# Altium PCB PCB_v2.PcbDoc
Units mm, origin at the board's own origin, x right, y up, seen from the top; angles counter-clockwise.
Board outline 61.5 x 35 mm, 2 copper layers (Top Layer, Bottom Layer); 42 components, 41 nets, 172 pads, 28 vias.
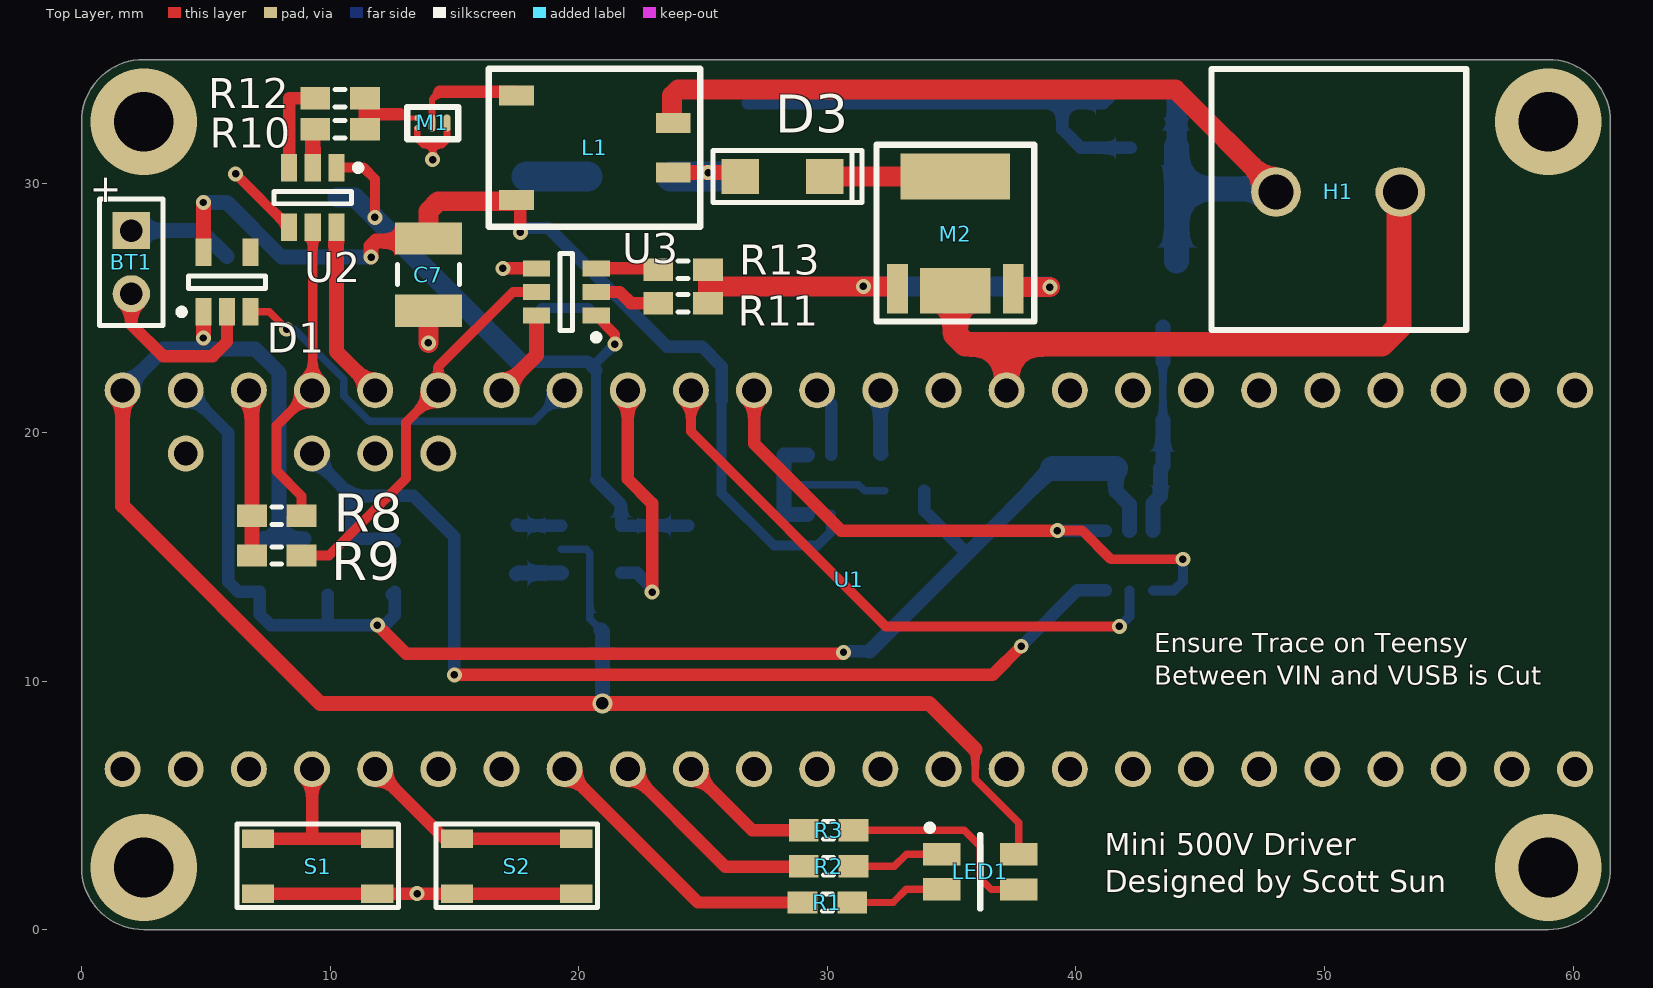
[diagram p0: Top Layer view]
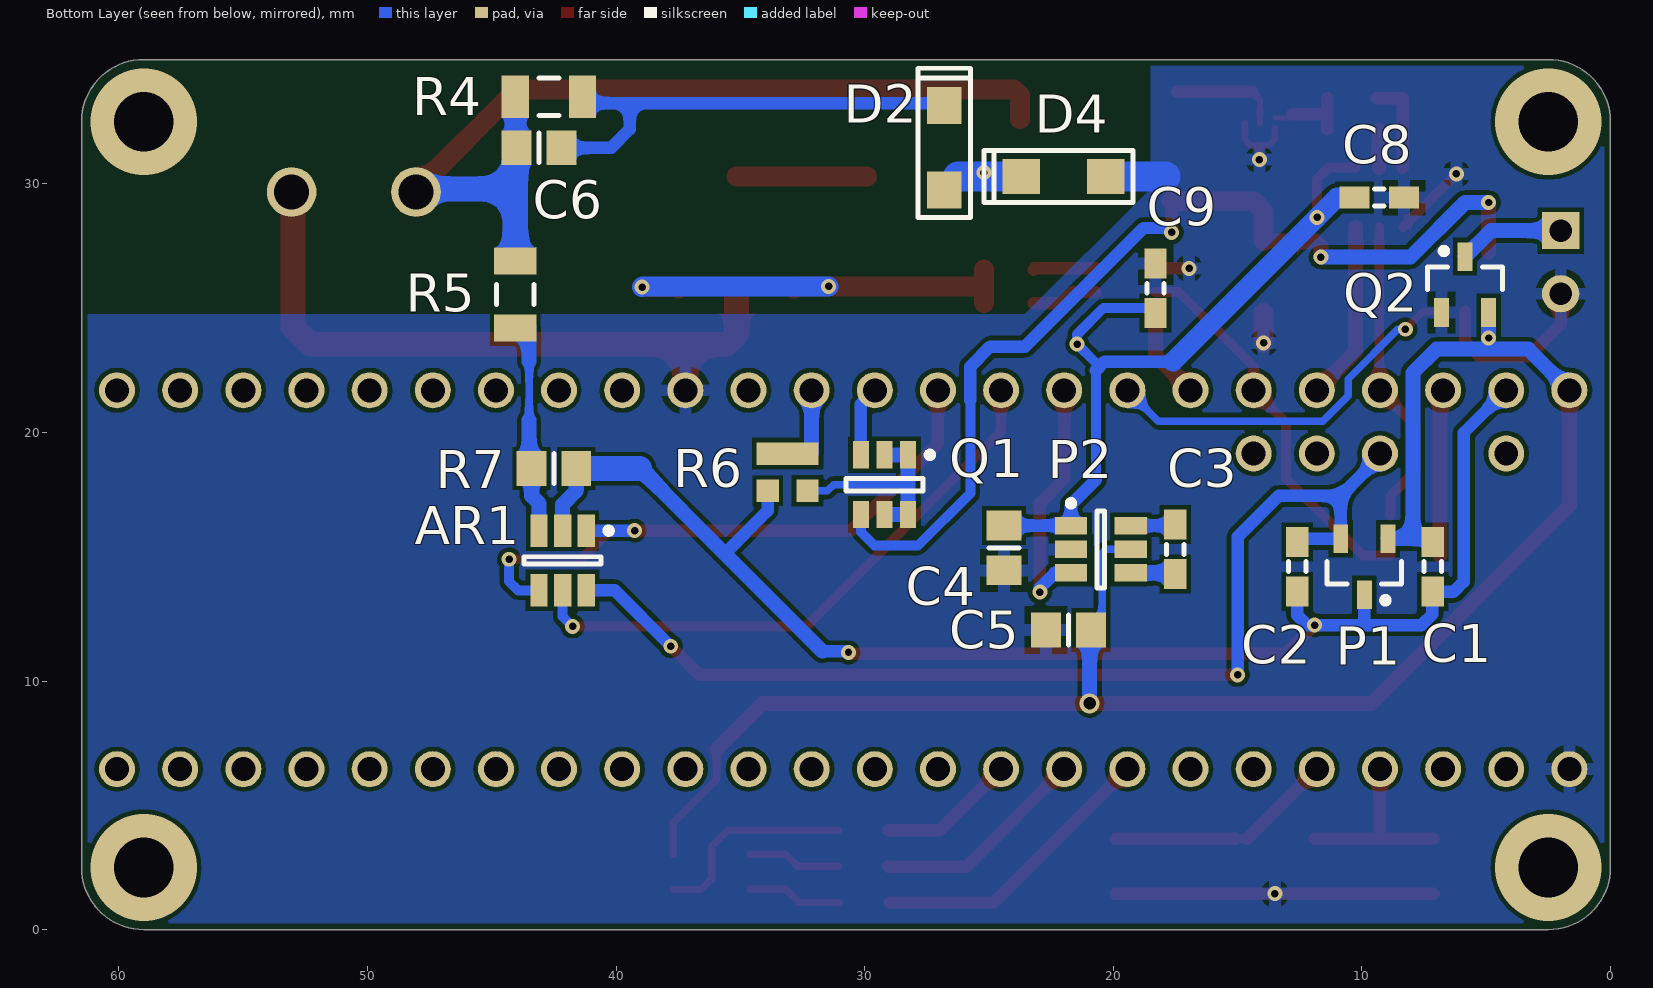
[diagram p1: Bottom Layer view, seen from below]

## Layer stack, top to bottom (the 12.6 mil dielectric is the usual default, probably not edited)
Top Solder: solder mask 0.0102, Solder Resist, Dk 3.5
Top Layer: signal copper 0.0356
Dielectric 1: dielectric 0.32, FR-4, Dk 4.8
Bottom Layer: signal copper 0.0356
Bottom Solder: solder mask 0.0102, Solder Resist, Dk 3.5

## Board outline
59,35 cw(c59,32.5) 61.5,32.5 61.5,2.5 cw(c59,2.5) 59,0 2.5,0 cw(c2.5,2.5) 0,2.5 0,32.5 cw(c2.5,32.5) 2.5,35

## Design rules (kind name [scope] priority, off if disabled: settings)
BoardOutlineClearance [All] p1: gap=0.2 ignorepadtopadclearanceinfootprint=FALSE
Clearance [All] p1: gap=0.178 ignorepadtopadclearanceinfootprint=FALSE
ComponentClearance ComponentClearance_1 [InComponent('U1')] p1: gap=0 collisioncheckmode=3 verticalgap=0 showdistances=FALSE
ComponentClearance [All] p2: gap=0.254 collisioncheckmode=3 verticalgap=0.254 showdistances=FALSE
HoleSize [All] p1: absolutevalues=TRUE maxlimit=2.54 minlimit=0.2 maxpercent=80.000 minpercent=20.000
MinimumAnnularRing [All] p1: minimumring=0.076
MinimumSolderMaskSliver [All] p1: minsoldermaskwidth=0.1
PolygonConnect [All] p1: connectstyle=Relief reliefconductorwidth=0.5 reliefentries=4 polygonreliefangle="90 Angle" airgapwidth=0.254
RoutingVias [All] p1: holewidth=1.5 width=1.27 viastyle="Through Hole" minholewidth=0.127 minwidth=0.3 maxholewidth=2.54 maxwidth=5
SolderMaskExpansion [All] p1: expansion=0.102
Width [All] p1: maxlimit=2 minlimit=0.1 preferedwidth=0.2
27 further rules are at their usual default settings.

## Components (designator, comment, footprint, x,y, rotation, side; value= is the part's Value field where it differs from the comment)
AR1 "OPA320" SOT23-6_M 42.15,14.85 r270 bottom
BT1 "Battery" BAT-2 2,26.85 r270 top
C1 "Cap Semi" 0603 7.15,14.6 r90 bottom value=100nF
C2 "Cap Semi" 0603 12.6,14.6 r90 bottom value=100nF
C3 "Cap Semi" 0603 17.5,15.3 r90 bottom value=1uF
C4 "Cap Semi" 6-0805_N 24.396,15.354 r90 bottom value=22uF
C5 "Cap Semi" 6-0805_N 21.8,12.05 r180 bottom value=10uF
C6 "Cap Semi" 6-0805_N 43.1,31.45 r0 bottom value=1nF
C7 "Cap Semi" C1210_N 13.95,26.35 r90 top value=100uF
C8 "Cap Semi" 0603 9.3,29.45 r0 bottom value=100nF
C9 "Cap Semi" 0603 18.3,25.8 r270 bottom value=100nF
D1 "LTC4411" SOT23-5 5.85,26.05 r90 top
D2 "HS1MLWRVG" sub-SMA 26.8,31.45 r90 bottom
D3 "HS1MLWRVG" sub-SMA 28.2,30.3 r0 top
D4 "HS1MLWRVG" sub-SMA 22,30.3 r0 bottom
H1 "1792863 Block" PHX_BLOCK_SMALLER 48.05,29.673 r0 top
L1 "Coupled Inductor" "CJ5143 Inductor" 17.9,31.45 r0 top
LED1 "150141M173100" 3528_A 36.15,2.325 r0 top
M1 "EPC2012C" EPC2012C 13.5,32.246 r0 top
M2 "GS66506" GS66506T 35.15,29.8 r0 top
P1 "REF3033" SOT23_N 9.9,14.6 r270 bottom
P2 "LTC1754-5" SOT23-6_M 20.5,15.3 r180 bottom
Q1 "IRFTS9342TRPBF" SOT23-6_N 29.2,17.9 r270 bottom
Q2 "DMP1045U" SOT23_N 5.85,25.95 r90 bottom
R1 "Res1" 0603 30,1.091 r0 top value=400
R2 "Res1" 0603 30.05,2.546 r0 top value=400
R3 "Res1" 0603 30.05,4 r0 top value=400
R4 "Res1" C1206 42.7,33.5 r0 bottom value=20K
R5 "Res1" C1206 44.05,25.55 r90 bottom value=120M
R6 "R2012A" R2012A 31.8,19.6 r0 bottom
R7 "Res1" 6-0805_N 42.5,18.55 r0 bottom value=634K
R8 "Res1" 0603 7.85,16.65 r180 top value=100K
R9 "Res1" 0603 7.85,15.05 r180 top value=100K
R10 "Res1" 0603 10.4,32.2 r180 top value=5
R11 "Res1" 0603 24.2,25.2 r0 top value=10
R12 "Res1" 0603 10.4,33.45 r180 top value=1
R13 "Res1" 0603 24.2,26.55 r0 top value=4
S1 "TL3365" TL3365 9.45,2.45 r0 top
S2 "TL3365" TL3365 17.45,2.45 r0 top
U1 "Teensy 3.5" "Teensy 3.6" 31.75,13.95 r0 top
U2 "LM5114" SOT23-6_N 9.3,29.45 r270 top
U3 "LM5114" SOT23-6_N 19.5,25.65 r180 top

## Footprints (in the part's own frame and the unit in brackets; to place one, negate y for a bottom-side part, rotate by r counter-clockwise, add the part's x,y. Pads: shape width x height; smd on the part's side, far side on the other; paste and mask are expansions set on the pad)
6-0805_N [mm] "Chip Resistor, Body 2.0x1.2mm, IPC Medium Density"
  rect 1.2x1.4 smd: 1(-0.9,0) 2(0.9,0)
  silkscreen extent 0,-0.6 0,0.6, body extent -1.07,-0.7 1.07,0.7, height 0.7
0603 [mm]
  rect 1.2x0.9 smd: 1(-1,0) 2(1,0)
  silkscreen extent -0.2,-0.35 0.2,0.35, body extent -0.85,-0.47 0.85,0.48, height 0.9
3528_A [mm] "Chip LED, 4-Leads, Body 2.8x3.5mm (max), Pitch 1.42mm, IPC Medium Density"
  rect 1.5x0.9 smd: 1(1.55,0.707) 2(1.55,-0.71) 3(-1.55,0.707) 4(-1.55,-0.707)
  silkscreen extent -2.15,-1.5 0.03,1.9, body extent -1.75,-1.4 1.75,1.4, height 1.87
BAT-2 [mm] "Battery; 2 Leads"
  rect 1.5x1.5 hole 0.9: 1(-1.27,0)
  round 1.5 hole 0.9: 2(1.27,0)
  silkscreen extent -2.54,-1.27 2.54,1.27
C1206 [mm] "Chip Capacitor, Body 3.2x1.6mm, IPC High Density"
  rect 1.1x1.7 smd: 1(-1.35,0) 2(1.35,0)
  silkscreen extent -0.4,-0.75 0.4,0.75, body extent -1.7,-0.9 1.7,0.9, height 1.3
C1210_N [mm] "Chip Capacitor, Body 3.2x2.5mm, IPC Medium Density"
  rect 1.3x2.7 smd: 1(-1.45,0) 2(1.45,0)
  silkscreen extent -0.4,-1.25 0.4,1.25, body extent -1.7,-1.35 1.7,1.35, height 1.5
"CJ5143 Inductor" [mm]
  rect 1.4x0.8 smd: 1(-0.4,-2.1) 4(-0.4,2.1) 5(5.9,1) 6(5.9,-1)
  silkscreen extent -1.52,-3.17 6.98,3.17
EPC2012C [mm]
  round 0.234 smd mask+0.01: 1(0,0.409) 2(0,0)
  oval 0.284x0.693 smd mask-0.025: 3(0.6,0.205) 4(1.2,0.205)
  silkscreen extent -0.4,-0.45 1.65,0.85
GS66506T [mm]
  rect 4.4x1.84 smd: 1(0,0.5)
  rect 0.84x1.99 smd: 2(-2.33,-4.02) 4(2.33,-4.02)
  rect 2.83x1.84 smd: 3(0,-4.1)
  silkscreen extent -3.17,-5.33 3.17,1.78
PHX_BLOCK_SMALLER [mm]
  round 2 hole 1.4: 1(0,0) 2(5,0)
  silkscreen extent -2.6,-5.55 7.65,4.95
R2012A [mm] "Voltage Divider 0805 Footprint"
  rect 0.9x0.9 smd: 1(0.5,1.95) 3(2.1,1.95)
  rect 2.5x0.9 smd: 2(1.3,0.45)
  body extent 0.23,0.5 2.37,1.9, height 0.7
SOT23-5 [mm]
  rect 1.1x0.65 smd: 1(-1.2,0.95) 2(-1.2,0) 3(-1.2,-0.95) 4(1.2,-0.95) 5(1.2,0.95)
  silkscreen extent -1.32,-1.55 0.25,1.95, body extent -0.9,-1.55 0.9,1.55, height 1.45
SOT23-6_M [mm] "SOT23, 6-Leads, Body 2.9x1.6mm, Pitch 0.95mm, Lead Span 2.7mm, IPC Low Density"
  rect 1.3x0.7 smd: 1(-1.2,0.95) 2(-1.2,0) 3(-1.2,-0.95) 4(1.2,-0.95) 5(1.2,0) 6(1.2,0.95)
  silkscreen extent -1.32,-1.55 0.15,1.97, body extent -0.9,-1.55 0.9,1.55, height 1.45
SOT23-6_N [mm] "SOT23, 6-Leads, Body 2.9x1.6mm, Pitch 0.95mm, Lead Span 2.7mm, IPC Medium Density"
  rect 1.1x0.65 smd: 1(-1.2,0.95) 2(-1.2,0) 3(-1.2,-0.95) 4(1.2,-0.95) 5(1.2,0) 6(1.2,0.95)
  silkscreen extent -1.32,-1.55 0.25,1.95, body extent -0.9,-1.55 0.9,1.55, height 1.45
SOT23_N [mm] "SOT23, 3-Leads, Body 2.9x1.3mm, Pitch 0.95mm, Lead Span 2.3mm - Reverse Pinning, IPC Medium Density"
  rect 1.15x0.6 smd: 1(1.125,0) 2(-1.125,-0.95) 3(-1.125,0.95)
  silkscreen extent -0.2,-1.5 1.47,1.5, body extent -0.7,-1.5 0.7,1.5, height 1.1
sub-SMA [mm]
  rect 1.5x1.4 smd: A(-1.7,0) K(1.7,0)
  silkscreen extent -2.8,-1.05 3.2,1.05
"Teensy 3.6" [mil]
  round 57 hole 38: 0/RX(-1085,-295) 1/TX(-985,-295) 2(-885,-295) 3/CANTX(-785,-295) 3V3(215,-295) 3V3_LO(-985,305) 4/CANRX(-685,-295) 5(-585,-295) 6(-485,-295) 7(-385,-295) 8(-285,-295) 9/CS(-185,-295) 10/CS(-85,-295) 11/MOSI(15,-295) 12/MISO(115,-295) 13/SCK(115,305) 14/A0(15,305) 15/A1(-85,305) 16/A2(-185,305) 17/A3(-285,305) 18/A4/SDA(-385,305) 19/A5/SCL(-485,305) 20/A6(-585,305) 21/A7(-685,305) 21/DAC0(415,305) 22/A8(-785,305) 23/A9(-885,305) 24(315,-295) 25(415,-295) 26(515,-295) 27(615,-295) 28(715,-295) 29(815,-295) 30(915,-295) 31/A12(1015,-295) 32/A13(1115,-295) 33/A14(1115,305) 34/A15(1015,305) 35/A16(915,305) 36/A17(815,305) 37/A18(715,305) 38/A19(615,305) 39/A20(515,305) A10(-785,205) A11(-685,205) A22/DAC1(315,305) AGND(-1085,305) AREF(-885,205) GND(-1185,-295) GND2(215,305) VIN(-1185,305) VUSB(-1085,205)
TL3365 [mm] "Pushbutton"
  rect 1.3x0.75 smd: 1(-2.35,-1) 2(2.45,-1) 3(-2.35,1.2) 4(2.45,1.2)
  silkscreen extent -3.2,-1.55 3.3,1.8

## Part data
AR1: library part "OPA320 Op Amp", "FET Operational Amplifier"
BT1: "Multicell Battery"
C1 C2 C3 C4 C5 C6 C7 C8 C9: "Capacitor (Semiconductor SIM Model)"
D1: library part "LTC4411 Ideal Diode", "LTC4411 Ideal Diode"
D2 D3 D4: library part "HS1MLWRVG Diode", "1kV fast diode"
H1: library part "1792863 1X2 Block", "Terminal Block, 2-Pin, 1792863"
L1: library part "CJ5143 Coupled Inductor", "1:15 Coupled Inductor"
LED1: library part CMP-1431-00001-1, "SMD Full-Color Top LED, WL-SFTW, Red & Green & Blue", Color="Red & Green & Blue", Manufacturer="Wuerth Elektronik"
M1: library part "EPC2012C GaNFET", "200V GaNFET Die"
M2: library part "GS66506 GaNFET", "650V GaNFET"
P1: library part "REF3030 3V Reference", "3.3V Reference"
P2: library part "LTC1754-5 Charge Pump", "5V Charge Pump"
Q1: library part "IRFTS9342TRPBF MOSFET", "30V, 5.8A, P-Channel MOSFET"
Q2: library part "DMP1045U PMOS", "P-Channel MOSFET"
R1 R2 R3 R4 R5 R7 R8 R9 R10 R11 R12 R13: "Resistor"
R6: library part "R2012A Voltage Divider", "Voltage Divider"
S1 S2: library part "TL3365 Pushbutton", "Pushbutton"
U1: library part TEENSY_3.6, "Teensy 3.6 Microcontroller"
U2 U3: library part "LM5114 Gate Driver", "Gate Driver"

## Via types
v1: diameter 0.6, hole 0.3, Top Layer to Bottom Layer, 23 vias
v2: diameter 4.3, hole 2.4, Top Layer to Bottom Layer, 4 vias
v3: diameter 0.8, hole 0.5, Top Layer to Bottom Layer, 1 vias

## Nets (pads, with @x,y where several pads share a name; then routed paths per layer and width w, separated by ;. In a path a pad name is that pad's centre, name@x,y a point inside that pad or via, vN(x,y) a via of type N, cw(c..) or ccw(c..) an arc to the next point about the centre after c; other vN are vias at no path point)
3.3V: R8.2 R9.2 U1.3V3_LO | length 6.7
  Top Layer w0.6: U1.3V3_LO 6.85,21.578 R8.2 R9.2
5V: C4.2 C8.2 C9.2 P2.1 U2.1 U3.1 | length 32.4
  Top Layer w0.4: U2.1 11.35,30.65 11.8,30.2 v1(11.8,28.65) ; U3.1 21.45,23.95 v1(21.45,23.55)
  Bottom Layer w0.4: C9.2 18.5,25 20.4,25 21.45,23.95 v1(21.45,23.55) 20.75,22.85 ; 20.7,18.1 20.7,22.5
  Bottom Layer w0.5: 17.6,22.85 20.35,22.85 20.7,22.5 ; 20.7,18.1 21.7,17.1 P2.1 21.704,16.254 C4.2
  Bottom Layer w0.8: C8.2 11,29.45 v1(11.8,28.65) 17.6,22.85
5V_S\H\D\N\: P2.3 U1.18/A4/SDA | length 10.2
  Top Layer w0.5: U1.18/A4/SDA 21.971,18.129 22.95,17.15 v1(22.95,13.575)
  Bottom Layer w0.5: P2.3 22.35,14.35 22.95,13.75 v1(22.95,13.575)
A0: R6.2 U1.14/A0 | length 2.6
  Bottom Layer w0.6: U1.14/A0 32.131,19.169 R6.2@32.15,19.15
A2: AR1.1 AR1.4 U1.16/A2 | length 25.5
  Top Layer w0.4: v1(39.25,16.05) 40.25,16.05 41.4,14.9 v1(44.3,14.9)
  Top Layer w0.5: U1.16/A2 27.051,19.549 30.55,16.05 v1(39.25,16.05)
  Bottom Layer w0.4: AR1.4 43.95,13.65 44.3,14 v1(44.3,14.9)
  Bottom Layer w0.5: v1(39.25,16.05) AR1.1
A3.3V: AR1.6 C2.2 P1.2 U1.AREF | length 43.9
  Top Layer w0.5: v1(15,10.25) 36.65,10.25 v1(37.8,11.4)
  Bottom Layer w0.5: U1.AREF 9.271,19.029 10.85,17.45 ; C2.2 12.475,15.725 P1.2 10.85,17.45 ; v1(15,10.25) 15,15.8 13.35,17.45 10.85,17.45 ; v1(37.8,11.4) 40.05,13.65 AR1.6
AGND: AR1.2 C1.1 C2.1 P1.1 R6.3 R7.1 U1.AGND | length 58.1
  Top Layer w0.5: v1(11.9,12.25) 13.05,11.1 30.6,11.1 v1(30.65,11.15)
  Bottom Layer w0.5: U1.AGND 5.9,19.988 5.9,14 6.312,13.588 7.162,13.588 7.162,12.688 7.6,12.25 9.9,12.25 ; P1.1 9.9,12.25 ; C2.1@12.475,13.475 C2.1 12.6,12.65 12.2,12.25 v1(11.9,12.25) 9.9,12.25 ; v1(30.65,11.15) 30.7,11.2 31.7,11.2 ; R6.3 33.9,16.85 35.625,15.125
  Bottom Layer w0.6: 31.7,11.2 35.625,15.125 39.05,18.55 ; R7.1 41.6,17.65 42.15,17.1 AR1.2
  Bottom Layer w1: 39.05,18.55 R7.1
B\A\T\T\_\S\E\N\S\E\: Q1.3 U1.15/A1 | length 2.8
  Bottom Layer w0.5: U1.15/A1 30.15,21.138 Q1.3
D_SHDN: D1.3 U1.19/A5/SCL | length 15.4
  Top Layer w0.3: D1.3 7.55,24.85 v1(8.25,24.15)
  Bottom Layer w0.3: v1(8.25,24.15) 8.55,24.15 10.55,22.15 10.55,21.471 11.571,20.45 18.184,20.45 U1.19/A5/SCL
GND: BT1.2 C4.1 C5.1 C7.1 C8.1 C9.1 D1.2 D4.A H1.2 M1.2 M1.4 M2.3 P2.2 Q2.3 S1.1 S1.2 S2.1 S2.2 U1.GND U1.GND2 U2.4 U3.4 | length 58.4
  Top Layer w0.25: M1.2@13.5,32.235 13.5,31.8 13.75,31.55 14.125,31.55 ; v1(14.125,30.975) 14.125,31.55 ; M1.4 14.7,31.75 14.5,31.55 14.125,31.55
  Top Layer w0.4: v1(6.2,30.4) U2.4
  Top Layer w0.5: BT1.2 2,24.35 3.278,23.072 5.272,23.072 5.85,23.65 D1.2 ; S1.1 S1.2 v1(13.5,1.45) S2.1 S2.2 ; v1(16.95,26.6) U3.4
  Top Layer w0.8: v1(13.95,23.6) C7.1@13.95,24.8
  Top Layer w1: M2.3 35.15,23.95 35.55,23.55 37.211,23.55 ; U1.GND2 37.211,23.55 ; H1.2@53,29.8 53,24.25 52.3,23.55 37.211,23.55
  Bottom Layer w1.2: 17.9,30.3 D4.A D4.A@20.35,30.3
L\O\A\D\_\S\H\D\N\: AR1.5 U1.17/A3 | length 23.8
  Top Layer w0.4: U1.17/A3 24.511,20.039 32.35,12.2 v1(41.75,12.2)
  Bottom Layer w0.4: v1(41.75,12.2) 42.15,12.6 AR1.5
NetAR1_3: AR1.3 R5.1 R7.2 | length 8.4
  Bottom Layer w0.3: 43.5,20.5 43.5,22.85
  Bottom Layer w0.6: AR1.3 43.1,17.15 43.4,17.45 R7.2 43.5,18.65 43.5,20.5 ; 43.5,22.85 R5.1@43.5,24.25
NetBT1_1: BT1.1 Q2.1 | length 4.3
  Bottom Layer w0.6: BT1.1 4.805,28.12 Q2.1
NetC3_1: C3.1 P2.4 | length 1.8
  Bottom Layer w0.6: C3.1 17.55,14.35 P2.4
NetC3_2: C3.2 P2.6 | length 1.8
  Bottom Layer w0.5: C3.2 17.55,16.25 P2.6
NetC6_1: C6.1 D2.K R4.1 | length 18.8
  Bottom Layer w0.5: D2.K@26.8,33.25 39.45,33.25 ; R4.1 41.1,33.25 39.45,33.25 ; C6.1 40.2,31.45 39.45,32.2 39.45,33.25
NetC6_2: C6.2 H1.1 L1.5 R4.2 R5.2 | length 37.5
  Top Layer w0.8: L1.5@23.75,32.6 23.75,33.55 24,33.8 44,33.8 H1.1@48,29.8
  Bottom Layer w0.8: C6.2@44.05,31.5 R4.2
  Bottom Layer w1: R5.2 44.05,29.8 ; C6.2@44.05,31.5 44.05,29.8 ; H1.1@48,29.8 44.05,29.8
NetC7_2: C7.2 D1.5 L1.1 Q1.4 | length 40.6
  Top Layer w0.5: v1(17.65,28.05) L1.1@17.65,29.3
  Top Layer w0.6: D1.5 v1(4.9,29.25) ; v1(11.65,27.05) 11.65,27.5 11.85,27.7 C7.2@13.95,27.7
  Top Layer w0.8: C7.2@13.95,27.7 C7.2 13.95,28.9 14.35,29.3 L1.1@17.65,29.3
  Bottom Layer w0.4: 25.75,21.3 25.75,17.55 27.85,15.45 29.6,15.45 30.15,16 Q1.4
  Bottom Layer w0.5: v1(17.65,28.05) 17.825,28.225 18.775,28.225 23.55,23.45 24.95,23.45 25.75,22.65 25.75,21.3
  Bottom Layer w0.6: v1(4.9,29.25) 5.85,29.25 8.05,27.05 v1(11.65,27.05)
NetD2_A: D2.A D3.A D4.K L1.6 | length 6
  Top Layer w0.6: L1.6 v1(25.2,30.45) 25.9,30.45 26.05,30.3 D3.A
  Bottom Layer w0.6: D4.K@23.6,30.3 D4.K ; D2.A@26.25,30.3 D2.A@26.65,29.9
  Bottom Layer w1.2: D4.K D2.A@26.25,30.3
NetD3_K: D3.K M2.1 | length 5.3
  Top Layer w0.8: D3.K M2.1
NetL1_4: L1.4 M1.3 | length 4.4
  Top Layer w0.25: M1.3 14.1,33.4 14.4,33.7
  Top Layer w0.5: 14.4,33.7 L1.4@17.45,33.7
NetLED1_2: LED1.2 R3.2 | length 8.4
  Top Layer w0.3: R3.2 35.5,4 36.15,3.35 36.15,2.05 36.585,1.615 LED1.2
NetLED1_3: LED1.3 R2.2 | length 3.8
  Top Layer w0.3: R2.2 32.696,2.546 33.183,3.033 LED1.3
NetLED1_4: LED1.4 R1.2 | length 3.8
  Top Layer w0.3: R1.2 32.641,1.091 33.168,1.618 LED1.4
NetM1_1: M1.1 R10.1 R12.1 | length 3.2
  Top Layer w0.2: 12.809,32.8 12.955,32.655 M1.1
  Top Layer w0.5: R10.1 R12.1 ; 11.65,32.8 12.809,32.8
NetM2_2: M2.2 M2.4 R11.2 R13.2 | length 17.7
  Top Layer w0.8: R11.2 R13.2 ; 25.5,25.875 v1(31.45,25.875) 32.725,25.875 M2.2 ; M2.4 37.55,25.85 v1(38.95,25.85)
  Bottom Layer w0.8: v1(31.45,25.875) 38.925,25.875 v1(38.95,25.85)
NetQ1_1: Q1.1 Q1.2 Q1.5 Q1.6 R6.1 | length 8.5
  Bottom Layer w0.3: 28.25,17.9 31.25,17.9 31.5,17.65 R6.1
  Bottom Layer w0.6: Q1.5 Q1.6 28.25,17.9 Q1.1 Q1.2
NetR1_1: R1.1 U1.6 | length 11.8
  Top Layer w0.5: U1.6 24.797,1.091 R1.1
NetR2_1: R2.1 U1.7 | length 8.7
  Top Layer w0.5: U1.7 25.9,2.528 29.032,2.528 R2.1
NetR3_1: R3.1 U1.8 | length 5.6
  Top Layer w0.5: U1.8 26.968,4 R3.1
NetR10_2: R10.2 U2.2 | length 1.6
  Top Layer w0.4: R10.2@9.3,32.15 R10.2@9.35,32.2
  Top Layer w0.6: U2.2 R10.2@9.3,32.15
NetR11_1: R11.1 U3.2 | length 2.7
  Top Layer w0.5: U3.2 21.65,25.65 22.1,25.2 R11.1
NetR12_2: R12.2 U2.3 | length 3.8
  Top Layer w0.5: U2.3 8.35,33.45 R12.2
NetR13_1: R13.1 U3.3 | length 2.5
  Top Layer w0.5: U3.3 23.15,26.6 R13.1
NetS1_3: S1.3 S1.4 U1.2 | length 8.1
  Top Layer w0.5: S1.3 9.25,3.65 ; U1.2@9.743,6.457 U1.2 9.271,3.671 9.25,3.65 ; S1.4 9.25,3.65
NetS2_3: S2.3 S2.4 U1.3/CANTX | length 9.3
  Top Layer w0.3: S2.3@14.618,3.65 S2.3
  Top Layer w0.5: U1.3/CANTX S2.3@14.618,3.65 ; S2.3 S2.4
P\_\E\N\: R8.1 U1.23/A9 U2.5 | length 12.6
  Top Layer w0.4: R8.1 8.85,17.45 7.85,18.45 7.85,20.276 U1.23/A9 9.3,21.726 U2.5
P_SWITCH: U1.22/A8 U2.6 | length 7.2
  Top Layer w0.6: U2.6 10.25,23.258 U1.22/A8
S\_\E\N\: R9.1 U1.21/A7 U3.5 | length 15.7
  Top Layer w0.4: R9.1 9.95,15.05 13.05,18.15 13.05,20.396 U1.21/A7 14.351,22.651 17.35,25.65 U3.5
S_SWITCH: U1.20/A6 U3.6 | length 3.6
  Top Layer w0.6: U1.20/A6 18.3,23.106 U3.6
VCC: C1.2 C5.2 D1.1 LED1.1 P1.3 P2.5 Q2.2 U1.VIN | length 73.8
  Top Layer w0.3: 35.95,7.25 35.95,6.05 37.7,4.3 LED1.1
  Top Layer w0.6: U1.VIN@1.747,21.697 U1.VIN 1.651,17.049 9.6,9.1 v3(20.95,9.1) 34.1,9.1 35.95,7.25 ; v1(4.9,23.8) D1.1
  Bottom Layer w0.3: P2.5 20.3,15.3 20.45,15.15 20.45,12.5 C5.2
  Bottom Layer w0.6: U1.VIN 3.304,23.35 7,23.35 7.95,22.4 7.95,15.725 ; 4.9,23.45 Q2.2 ; C1.2 7.275,15.725 7.95,15.725 ; P1.3 7.95,15.725 ; C5.2 20.95,12 v3(20.95,9.1)
pads on no net: D1.4 U1.0/RX U1.1/TX U1.3V3 U1.4/CANRX U1.5 U1.9/CS U1.10/CS U1.11/MOSI U1.12/MISO U1.13/SCK U1.21/DAC0 U1.24 U1.25 U1.26 U1.27 U1.28 U1.29 U1.30 U1.31/A12 U1.32/A13 U1.33/A14 U1.34/A15 U1.35/A16 U1.36/A17 U1.37/A18 U1.38/A19 U1.39/A20 U1.A10 U1.A11 U1.A22/DAC1 U1.VUSB
copper on no net:
  other v2: 2.5,2.5 59,2.5 2.5,32.5 59,32.5

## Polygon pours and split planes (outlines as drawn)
GND on Bottom Layer "Bottom-GND" (solid, remove dead copper, pour order 4): 0,35.5 0,0 61.65,0 61.65,24.75 23.55,24.75 18.5,29.8 18.5,35.5

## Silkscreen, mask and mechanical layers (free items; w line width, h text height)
Top Overlay:
  text "Ensure Trace on Teensy / Between VIN and VUSB is Cut" at 43.15,9.6 h1.3
  text "Mini 500V Driver / Designed by Scott Sun" at 41.15,1.2 h1.5
Mechanical 1:
  lines w0.2: 59,0 ccw(c59,2.5) 61.5,2.5 ; 59,0 2.5,0 cw(c2.5,2.5) 0,2.5 0,32.5 cw(c2.5,32.5) 2.5,35 59,35 cw(c59,32.5) 61.5,32.5 61.5,2.5 ; 59,0 59,0 ; 61.5,2.5 61.5,2.5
